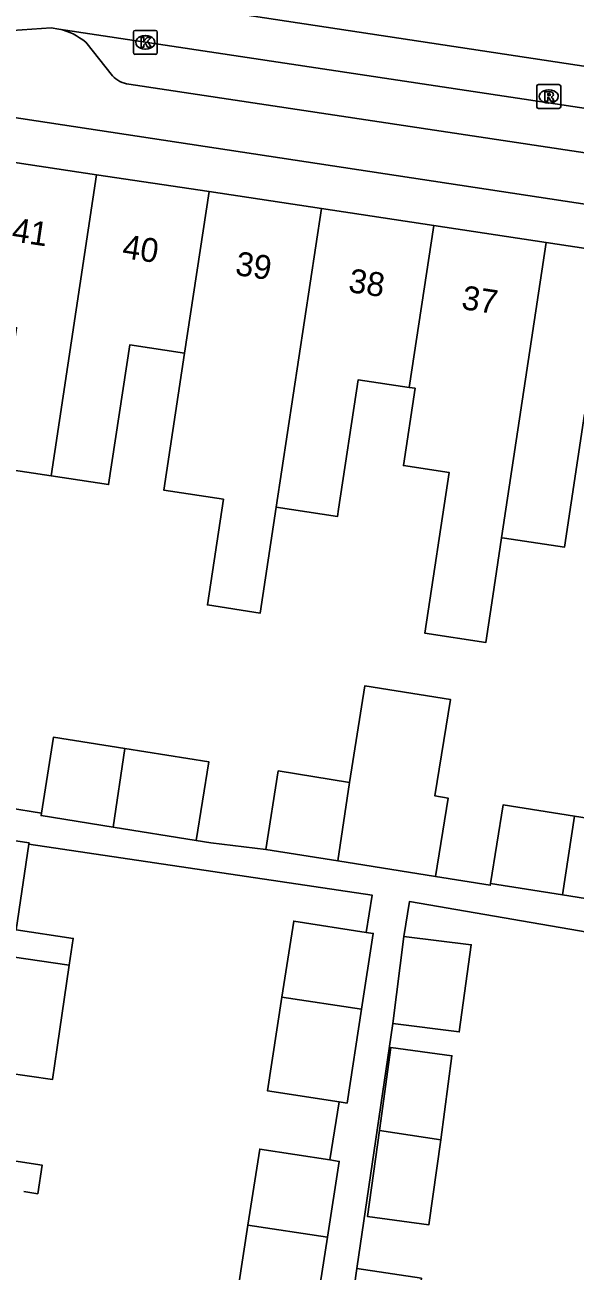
# Model space of a CAD drawing. Extents: x 162172 to 163187, y 382874 to 383684.
# Drawn here: x 162933.9 to 162956.9, y 383228.8 to 383280.9 of the extents above; entities that cross this region are included whole.
import ezdxf

# ---------------------------------------------------------------- set-up
doc = ezdxf.new("R2010")
doc.units = 0
for name, color, linetype in [('IMGEO_Kolk', 7, 'Continuous'), ('IMGEO_Pand', 7, 'Continuous'), ('IMGEO_Pand_nummerreeks', 7, 'Continuous'), ('IMGEO_Rijbaan_lokaal_gesloten', 7, 'Continuous'), ('IMGEO_Rioolput', 7, 'Continuous'), ('IMGEO_Voetpad_open', 7, 'Continuous')]:
    doc.layers.add(name, color=color, linetype=linetype)

msp = doc.modelspace()

# ---------------------------------------------------------------- linework, layer by layer
at = {"layer": 'IMGEO_Kolk'}
for p, q in [((162938.429, 383279.741), (162938.429, 383280.593)), ((162938.504, 383280.667), (162939.356, 383280.667)), ((162938.917, 383280.447), (162938.942, 383280.447)), ((162939.43, 383280.593), (162939.43, 383279.741)), ((162938.94, 383279.887), (162938.915, 383279.887)), ((162939.356, 383279.667), (162938.504, 383279.667))]:
    msp.add_line(p, q, dxfattribs=at)
for points in [[(162938.429, 383279.741), (162938.429, 383280.593)], [(162938.504, 383280.667), (162939.356, 383280.667)], [(162938.75, 383280.367), (162938.873, 383280.367), (162938.873, 383280.216), (162939.003, 383280.367), (162939.167, 383280.367), (162939.021, 383280.216), (162939.174, 383279.967), (162939.022, 383279.967), (162938.937, 383280.131), (162938.873, 383280.064), (162938.873, 383279.967), (162938.75, 383279.967), (162938.75, 383280.367)], [(162939.43, 383280.593), (162939.43, 383279.741)], [(162939.356, 383279.667), (162938.504, 383279.667)]]:
    msp.add_lwpolyline(points, dxfattribs=at)
for centre, start, end in [((162938.506, 383280.591), 91.552, 178.448), ((162938.506, 383280.591), 91.552, 178.448), ((162939.354, 383280.591), 1.552, 88.448), ((162939.354, 383280.591), 1.552, 88.448), ((162938.506, 383279.743), 181.552, 268.448), ((162938.506, 383279.743), 181.552, 268.448), ((162939.354, 383279.743), 271.552, 358.448), ((162939.354, 383279.743), 271.552, 358.448)]:
    msp.add_arc(centre, 0.0765, start, end, dxfattribs=at)
for centre, major_axis, ratio, start_param, end_param in [((162938.916, 383280.167), (-0.387, 0.002), 0.722429, 4.712389, 7.853982), ((162938.941, 383280.167), (-0.39, 0.002), 0.717154, 1.570796, 4.712389)]:
    msp.add_ellipse(centre, major_axis=major_axis, ratio=ratio, start_param=start_param, end_param=end_param, dxfattribs=at)
at = {"layer": 'IMGEO_Pand'}
for points in [[(162936.892, 383274.636), (162932.35, 383275.32)], [(162934.989, 383262.05), (162936.892, 383274.636)], [(162941.594, 383273.928), (162936.892, 383274.636)], [(162941.594, 383273.928), (162940.572, 383267.172)], [(162946.296, 383273.22), (162941.594, 383273.928)], [(162946.296, 383273.22), (162944.408, 383260.738)], [(162950.997, 383272.512), (162946.296, 383273.22)], [(162950.997, 383272.512), (162949.974, 383265.746)], [(162955.7, 383271.804), (162950.997, 383272.512)], [(162953.833, 383259.466), (162955.7, 383271.804)], [(162960.402, 383271.096), (162955.7, 383271.804)], [(162931.329, 383268.574), (162931.436, 383268.558), (162933.544, 383268.238), (162932.66, 383262.403), (162934.989, 383262.05)], [(162934.989, 383262.05), (162937.391, 383261.685), (162938.276, 383267.52), (162940.572, 383267.172)], [(162940.572, 383267.172), (162939.707, 383261.452), (162942.194, 383261.074), (162941.524, 383256.655), (162943.739, 383256.319), (162944.408, 383260.738)], [(162944.408, 383260.738), (162946.969, 383260.349), (162947.017, 383260.665), (162947.836, 383266.07), (162949.974, 383265.746)], [(162949.974, 383265.746), (162950.217, 383265.709), (162949.728, 383262.481), (162951.645, 383262.19), (162950.627, 383255.472), (162953.17, 383255.084), (162953.463, 383257.021), (162953.833, 383259.466)], [(162953.833, 383259.466), (162953.96, 383259.447), (162956.462, 383259.067), (162957.306, 383264.633), (162959.377, 383264.319)], [(162951.072, 383245.304), (162951.595, 383248.584), (162951.047, 383248.672), (162951.69, 383252.707), (162948.119, 383253.277), (162947.478, 383249.241)], [(162938.074, 383250.657), (162935.088, 383251.133), (162934.581, 383247.955)], [(162938.074, 383250.657), (162937.577, 383247.373)], [(162941.063, 383246.817), (162941.586, 383250.097), (162938.074, 383250.657)], [(162947.478, 383249.241), (162944.491, 383249.717), (162943.968, 383246.437)], [(162947.478, 383249.241), (162946.982, 383245.956)], [(162937.577, 383247.373), (162934.565, 383247.853), (162934.581, 383247.955)], [(162956.882, 383247.825), (162953.896, 383248.301), (162953.373, 383245.021)], [(162926.177, 383247.852), (162930.949, 383247.174), (162934.068, 383246.713), (162934.059, 383246.652)], [(162956.882, 383247.825), (162956.386, 383244.541)], [(162960.477, 383243.888), (162961, 383247.168), (162956.882, 383247.825)], [(162937.577, 383247.373), (162941.063, 383246.817)], [(162935.749, 383241.596), (162935.915, 383242.72), (162933.53, 383243.076), (162934.059, 383246.652)], [(162946.982, 383245.956), (162943.968, 383246.437)], [(162946.982, 383245.956), (162951.072, 383245.304)], [(162956.386, 383244.541), (162953.373, 383245.021)], [(162960.477, 383243.888), (162956.386, 383244.541)], [(162948.17, 383242.972), (162945.138, 383243.442), (162944.646, 383240.267)], [(162935.749, 383241.596), (162933.364, 383241.952), (162925.471, 383243.131)], [(162948.17, 383242.972), (162948.466, 383242.926), (162947.977, 383239.769)], [(162949.291, 383239.157), (162949.747, 383242.805)], [(162949.747, 383242.805), (162952.565, 383242.453), (162952.063, 383238.81), (162949.291, 383239.157)], [(162933.12, 383237.104), (162935.043, 383236.82), (162935.241, 383238.16), (162935.749, 383241.596)], [(162944.646, 383240.267), (162944.04, 383236.353), (162947.041, 383235.888)], [(162944.646, 383240.267), (162947.977, 383239.769)], [(162947.977, 383239.769), (162947.368, 383235.837), (162947.041, 383235.888)], [(162948.723, 383234.691), (162949.201, 383238.166), (162951.758, 383237.814), (162951.299, 383234.305)], [(162933.851, 383232.139), (162934.43, 383232.052), (162934.608, 383233.244), (162932.588, 383233.546), (162933.12, 383237.104)], [(162951.299, 383234.305), (162950.784, 383230.744), (162948.228, 383231.096), (162948.723, 383234.691)], [(162948.723, 383234.691), (162951.299, 383234.305)], [(162946.654, 383233.46), (162943.713, 383233.916), (162943.221, 383230.737)], [(162946.654, 383233.46), (162947.041, 383233.4), (162946.551, 383230.239)], [(162943.221, 383230.737), (162942.615, 383226.827), (162945.524, 383226.376)], [(162943.221, 383230.737), (162946.551, 383230.239)], [(162946.551, 383230.239), (162945.943, 383226.311), (162945.524, 383226.376)], [(162947.324, 383225.652), (162947.774, 383228.922)], [(162947.774, 383228.922), (162950.477, 383228.515), (162950.027, 383225.245)]]:
    msp.add_lwpolyline(points, dxfattribs=at)
at = {"layer": 'IMGEO_Rijbaan_lokaal_gesloten'}
for points in [[(162920.076, 383280.478), (162927.187, 383281.43), (162932.122, 383282.103), (162935.262, 383282.327), (162940.869, 383281.654), (162963.075, 383278.288), (162979.785, 383275.484), (162988.869, 383274.025), (162997.504, 383272.791), (163000.382, 383272.424), (163003.62, 383272.424), (163009.736, 383273.624), (163020.844, 383276.695), (163040.344, 383282.562), (163053.955, 383286.521), (163056.952, 383287.24)], [(162935.314, 383280.725), (162934.995, 383280.773), (162932.962, 383280.637), (162930.976, 383280.432), (162929.847, 383280.24), (162924.452, 383279.503)], [(162935.314, 383280.725), (162973.133, 383275.028), (162975.936, 383274.527)]]:
    msp.add_lwpolyline(points, dxfattribs=at)
at = {"layer": 'IMGEO_Rioolput'}
for p, q in [((162955.305, 383277.478), (162955.305, 383278.33)), ((162955.38, 383278.404), (162956.232, 383278.404)), ((162955.793, 383278.184), (162955.818, 383278.184)), ((162956.306, 383278.33), (162956.306, 383277.478)), ((162955.816, 383277.624), (162955.791, 383277.624)), ((162956.232, 383277.404), (162955.38, 383277.404))]:
    msp.add_line(p, q, dxfattribs=at)
for points in [[(162955.305, 383277.478), (162955.305, 383278.33)], [(162955.38, 383278.404), (162956.232, 383278.404)], [(162956.306, 383278.33), (162956.306, 383277.478)], [(162955.894, 383278.102), (162955.642, 383278.104), (162955.642, 383277.704)], [(162955.642, 383277.704), (162955.766, 383277.704), (162955.766, 383277.866), (162955.777, 383277.866)], [(162955.82, 383278.023), (162955.766, 383278.023), (162955.766, 383277.942)], [(162955.766, 383277.942), (162955.818, 383277.942)], [(162955.824, 383277.837), (162955.895, 383277.704), (162956.035, 383277.704), (162955.97, 383277.83)], [(162956.232, 383277.404), (162955.38, 383277.404)]]:
    msp.add_lwpolyline(points, dxfattribs=at)
for centre, radius, start, end in [((162955.382, 383278.328), 0.0765, 91.552, 178.448), ((162955.382, 383278.328), 0.0765, 91.552, 178.448), ((162956.23, 383278.328), 0.0765, 1.552, 88.448), ((162956.23, 383278.328), 0.0765, 1.552, 88.448), ((162955.776, 383277.813), 0.0533, 26.0293, 88.6989), ((162955.802, 383278.131), 0.19, 274.7715, 282.9687), ((162955.826, 383277.927), 0.0964, 77.0061, 93.1865), ((162955.84, 383277.984), 0.0378, 276.6634, 79.6772), ((162955.893, 383277.992), 0.109, 350.3612, 89.416), ((162955.891, 383277.992), 0.112, 277.5842, 350.9817), ((162955.875, 383277.777), 0.108, 29.5134, 73.7905), ((162955.382, 383277.48), 0.0765, 181.552, 268.448), ((162955.382, 383277.48), 0.0765, 181.552, 268.448), ((162956.23, 383277.48), 0.0765, 271.552, 358.448), ((162956.23, 383277.48), 0.0765, 271.552, 358.448)]:
    msp.add_arc(centre, radius, start, end, dxfattribs=at)
for centre, major_axis, ratio, start_param, end_param in [((162955.792, 383277.904), (-0.387, 0.002), 0.722429, 4.712389, 7.853982), ((162955.817, 383277.904), (-0.39, 0.002), 0.717154, 1.570796, 4.712389)]:
    msp.add_ellipse(centre, major_axis=major_axis, ratio=ratio, start_param=start_param, end_param=end_param, dxfattribs=at)
at = {"layer": 'IMGEO_Voetpad_open'}
for points in [[(162937.549, 383278.762), (162936.434, 383280.174)], [(162972.998, 383273.201), (162938.244, 383278.42)], [(162932.146, 383277.218), (162978.626, 383270.167)], [(162934.581, 383247.955), (162931.805, 383248.398)], [(162934.059, 383246.652), (162948.418, 383244.528), (162948.17, 383242.972)], [(162943.968, 383246.437), (162941.669, 383246.72), (162941.063, 383246.817)], [(162953.373, 383245.021), (162953.36, 383244.939), (162951.072, 383245.304)], [(162949.747, 383242.805), (162949.975, 383244.26), (162964.116, 383241.822)], [(162947.774, 383228.922), (162949.291, 383239.157)], [(162947.041, 383235.888), (162946.654, 383233.46)]]:
    msp.add_lwpolyline(points, dxfattribs=at)
for centre, radius, start, end in [((162934.767, 383278.199), 2.585, 49.8328, 77.7762), ((162938.413, 383279.642), 1.233, 225.4969, 262.1007)]:
    msp.add_arc(centre, radius, start, end, dxfattribs=at)

# ---------------------------------------------------------------- texts
at = {"layer": 'IMGEO_Pand_nummerreeks'}
for s, rotation, p in [('41', 351.4343, (162933.304, 383271.86)), ('40', 351.4361, (162937.927, 383271.163)), ('39', 351.4343, (162942.656, 383270.452)), ('38', 351.4343, (162947.391, 383269.738)), ('37', 351.4343, (162952.121, 383269.027))]:
    msp.add_text(s, height=1, rotation=rotation, dxfattribs=at).set_placement(p)

doc.saveas('drawing.dxf')
